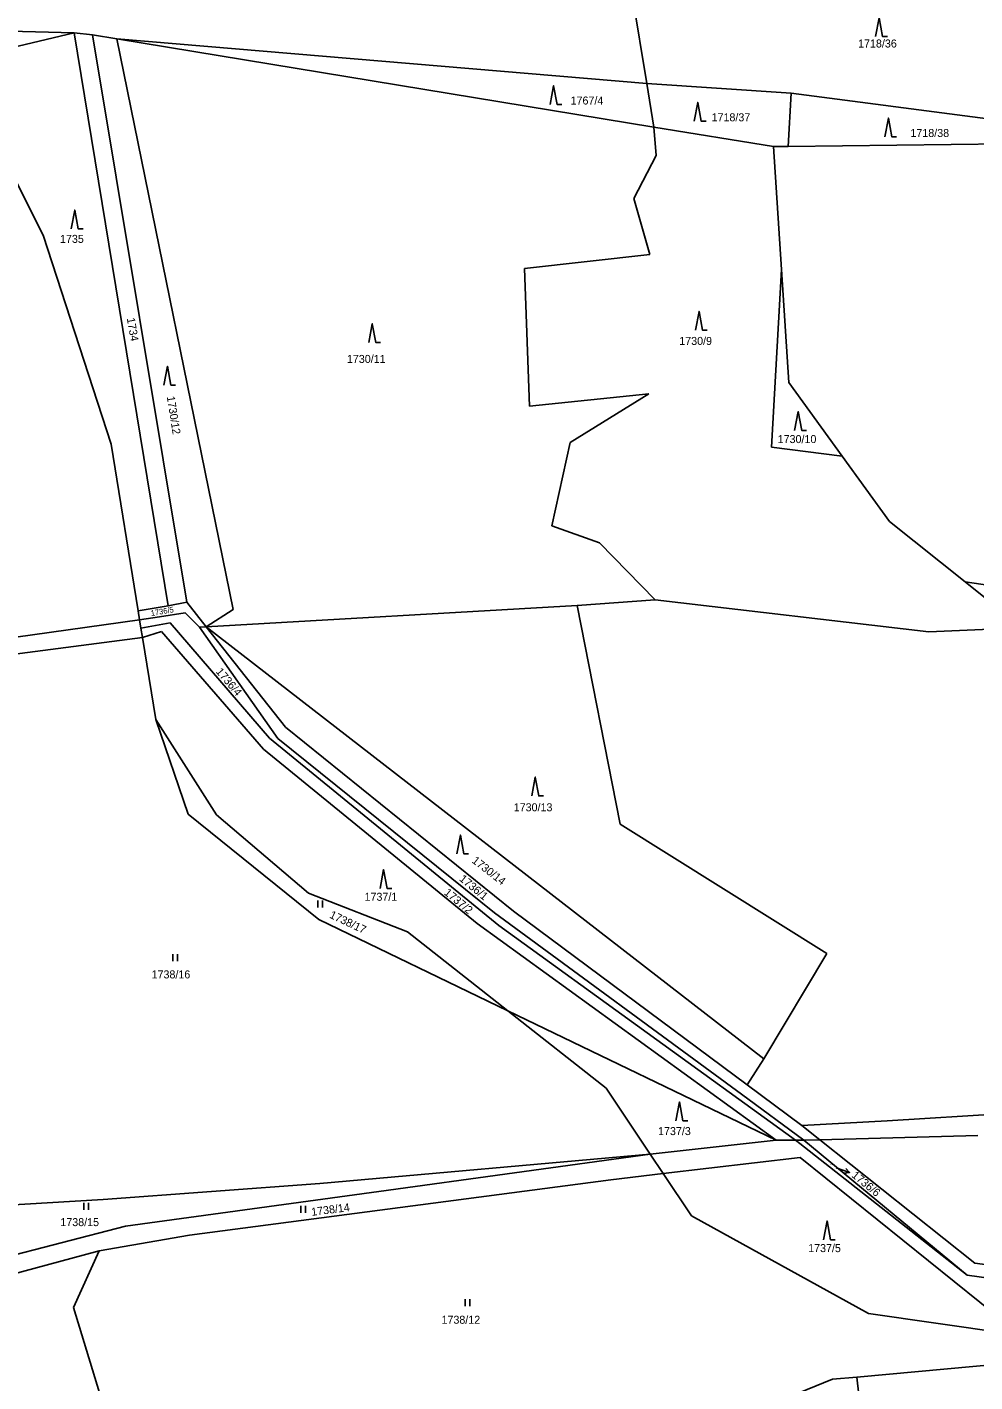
# Model space of a CAD drawing. Extents: x -609861 to -605046, y -1120287 to -1116307.
# Drawn here: x -609113.7 to -608912.5, y -1119290.5 to -1119002.8 of the extents above; entities that cross this region are included whole.
import ezdxf

# ---------------------------------------------------------------- set-up
doc = ezdxf.new("R2010")
doc.units = 0
for name, color, linetype in [('Vrstva 1', 7, 'Continuous'), ('Vrstva 2', 7, 'Continuous'), ('Vrstva 3', 7, 'Continuous'), ('Vrstva 7', 7, 'Continuous')]:
    doc.layers.add(name, color=color, linetype=linetype)

msp = doc.modelspace()

# ---------------------------------------------------------------- linework, layer by layer
at = {"layer": 'Vrstva 1'}
for p, q in [((-608982.13, -1119014.72), (-608989.22, -1118971.97)), ((-609131.7, -1119003.25), (-609103.64, -1119004)), ((-609103.64, -1119004), (-609128.87, -1119009.93)), ((-609099.81, -1119004.44), (-609103.64, -1119004)), ((-609083.72, -1119125.64), (-609103.64, -1119004)), ((-609094.64, -1119005.29), (-609099.81, -1119004.44)), ((-609079.74, -1119124.87), (-609099.81, -1119004.44)), ((-608982.13, -1119014.72), (-609094.64, -1119005.29)), ((-608980.59, -1119023.99), (-609094.64, -1119005.29)), ((-609094.64, -1119005.29), (-609069.91, -1119126.41)), ((-609110.25, -1119046.93), (-609128.87, -1119009.93)), ((-608982.13, -1119014.72), (-608951.45, -1119016.8)), ((-608980.59, -1119023.99), (-608982.13, -1119014.72)), ((-608952.08, -1119028.1), (-608951.45, -1119016.8)), ((-608951.45, -1119016.8), (-608909.69, -1119022.23)), ((-608980.16, -1119030.01), (-608980.59, -1119023.99)), ((-608955.23, -1119028.14), (-608980.59, -1119023.99)), ((-608952.08, -1119028.1), (-608955.23, -1119028.14)), ((-608955.23, -1119028.14), (-608953.52, -1119054.24)), ((-608849.32, -1119026.95), (-608952.08, -1119028.1)), ((-608984.88, -1119039.15), (-608980.16, -1119030.01)), ((-608981.44, -1119051.07), (-608984.88, -1119039.15)), ((-609095.85, -1119091.35), (-609110.25, -1119046.93)), ((-609008.06, -1119054.05), (-608981.44, -1119051.07)), ((-609006.99, -1119083.26), (-609008.06, -1119054.05)), ((-608955.61, -1119091.96), (-608953.52, -1119054.24)), ((-608953.52, -1119054.24), (-608951.95, -1119078.26)), ((-608981.66, -1119080.67), (-609006.99, -1119083.26)), ((-608998.4, -1119091), (-608981.66, -1119080.67)), ((-608951.95, -1119078.26), (-608940.64, -1119093.87)), ((-609090.09, -1119126.71), (-609095.85, -1119091.35)), ((-609002.27, -1119108.69), (-608998.4, -1119091)), ((-608940.64, -1119093.87), (-608955.61, -1119091.96)), ((-608940.64, -1119093.87), (-608930.6, -1119107.73)), ((-608992.18, -1119112.26), (-609002.27, -1119108.69)), ((-608930.6, -1119107.73), (-608914.57, -1119120.58)), ((-608980.37, -1119124.38), (-608992.18, -1119112.26)), ((-608859.5, -1119128.5), (-608914.57, -1119120.58)), ((-608914.57, -1119120.58), (-608902.38, -1119130.35)), ((-609083.72, -1119125.64), (-609090.09, -1119126.71)), ((-609089.78, -1119128.6), (-609090.09, -1119126.71)), ((-609079.74, -1119124.87), (-609083.72, -1119125.64)), ((-609075.62, -1119130.1), (-609079.74, -1119124.87)), ((-609075.62, -1119130.1), (-608996.93, -1119125.62)), ((-609069.91, -1119126.41), (-609075.62, -1119130.1)), ((-608996.93, -1119125.62), (-608980.37, -1119124.38)), ((-608987.74, -1119172.03), (-608996.93, -1119125.62)), ((-608980.37, -1119124.38), (-608922.25, -1119131.21)), ((-609089.78, -1119128.6), (-609167.83, -1119139.65)), ((-609085.55, -1119128), (-609089.78, -1119128.6)), ((-609089.49, -1119130.38), (-609089.78, -1119128.6)), ((-609083.32, -1119129.28), (-609089.49, -1119130.38)), ((-609080.1, -1119127.16), (-609085.55, -1119128)), ((-609062.21, -1119153.74), (-609083.32, -1119129.28)), ((-609077.04, -1119130.18), (-609080.1, -1119127.16)), ((-609089.17, -1119132.38), (-609147.89, -1119140.02)), ((-609089.17, -1119132.38), (-609089.49, -1119130.38)), ((-609089.17, -1119132.38), (-609085.13, -1119131.14)), ((-609086.34, -1119149.77), (-609089.17, -1119132.38)), ((-609085.13, -1119131.14), (-609063.51, -1119156.12)), ((-609075.62, -1119130.1), (-609077.04, -1119130.18)), ((-609060.45, -1119153.85), (-609077.04, -1119130.18)), ((-609058.8, -1119151.45), (-609075.62, -1119130.1)), ((-608957.29, -1119221.83), (-609075.62, -1119130.1)), ((-608922.25, -1119131.21), (-608902.38, -1119130.35)), ((-609079.46, -1119169.88), (-609086.34, -1119149.77)), ((-609073.46, -1119170.01), (-609086.34, -1119149.77)), ((-609010.38, -1119190.48), (-609058.8, -1119151.45)), ((-609013.5, -1119193.51), (-609062.21, -1119153.74)), ((-609014.45, -1119190.88), (-609060.45, -1119153.85)), ((-609063.51, -1119156.12), (-609018.13, -1119193.15)), ((-609051.71, -1119192.3), (-609079.46, -1119169.88)), ((-609053.95, -1119186.7), (-609073.46, -1119170.01)), ((-608943.9, -1119199.48), (-608987.74, -1119172.03)), ((-609032.91, -1119194.86), (-609053.95, -1119186.7)), ((-609011.59, -1119211.65), (-609051.71, -1119192.3)), ((-609018.13, -1119193.15), (-608954.62, -1119239.13)), ((-608962.02, -1119229.34), (-609014.45, -1119190.88)), ((-608960.8, -1119227.4), (-609010.38, -1119190.48)), ((-609011.59, -1119211.65), (-609032.91, -1119194.86)), ((-608950.54, -1119239.14), (-609013.5, -1119193.51)), ((-608957.29, -1119221.83), (-608943.9, -1119199.48)), ((-608954.62, -1119239.13), (-609011.59, -1119211.65)), ((-608990.73, -1119228.08), (-609011.59, -1119211.65)), ((-608960.8, -1119227.4), (-608957.29, -1119221.83)), ((-608949.19, -1119236.04), (-608960.8, -1119227.4)), ((-608981.37, -1119242.11), (-608990.73, -1119228.08)), ((-608948.75, -1119239.14), (-608962.02, -1119229.34)), ((-608931.11, -1119235), (-608864.15, -1119230.95)), ((-608949.19, -1119236.04), (-608931.11, -1119235)), ((-608945.41, -1119239.05), (-608949.19, -1119236.04)), ((-608954.62, -1119239.13), (-608981.37, -1119242.11)), ((-608950.54, -1119239.14), (-608954.62, -1119239.13)), ((-608948.75, -1119239.14), (-608950.54, -1119239.14)), ((-608949.6, -1119239.82), (-608950.54, -1119239.14)), ((-608945.41, -1119239.05), (-608948.75, -1119239.14)), ((-608948.75, -1119239.14), (-608914.13, -1119267.8)), ((-608911.88, -1119238.11), (-608945.41, -1119239.05)), ((-608912.5, -1119265.23), (-608945.41, -1119239.05)), ((-608981.37, -1119242.11), (-609051.54, -1119248.34)), ((-608981.37, -1119242.11), (-609038.99, -1119250.06)), ((-608978.62, -1119246.24), (-608981.37, -1119242.11)), ((-608914.13, -1119267.8), (-608949.6, -1119239.82)), ((-608978.62, -1119246.24), (-608949.58, -1119242.79)), ((-608949.58, -1119242.79), (-608902.64, -1119280.62)), ((-609079.22, -1119259.28), (-608989.72, -1119247.55)), ((-608989.72, -1119247.55), (-608978.62, -1119246.24)), ((-608972.62, -1119255.22), (-608978.62, -1119246.24)), ((-609051.54, -1119248.34), (-609097.54, -1119251.74)), ((-609038.99, -1119250.06), (-609092.75, -1119257.4)), ((-609097.54, -1119251.74), (-609121.14, -1119253.15)), ((-608935.03, -1119275.94), (-608972.62, -1119255.22)), ((-609092.75, -1119257.4), (-609120.66, -1119264.59)), ((-609098.34, -1119262.65), (-609079.22, -1119259.28)), ((-609120.49, -1119268.57), (-609098.34, -1119262.65)), ((-609098.34, -1119262.65), (-609103.8, -1119274.67)), ((-608887.71, -1119271.4), (-608914.13, -1119267.8)), ((-608885.64, -1119268.88), (-608912.5, -1119265.23)), ((-609103.8, -1119274.67), (-609095.64, -1119301.49)), ((-608902.64, -1119280.62), (-608935.03, -1119275.94)), ((-608896.35, -1119285.7), (-608937.56, -1119289.47)), ((-608942.71, -1119289.87), (-608953.44, -1119294.24)), ((-608937.56, -1119289.47), (-608942.71, -1119289.87)), ((-608937.56, -1119289.47), (-608931.03, -1119344.43))]:
    msp.add_line(p, q, dxfattribs=at)
at = {"layer": 'Vrstva 3'}
for p, q in [((-609051.97, -1119188.24), (-609051.97, -1119189.74)), ((-609050.97, -1119189.74), (-609050.97, -1119188.24)), ((-609082.71, -1119199.61), (-609082.71, -1119201.11)), ((-609081.71, -1119201.11), (-609081.71, -1119199.61)), ((-609101.64, -1119252.42), (-609101.64, -1119253.92)), ((-609100.64, -1119253.92), (-609100.64, -1119252.42)), ((-609055.56, -1119253.09), (-609055.56, -1119254.59)), ((-609054.56, -1119254.59), (-609054.56, -1119253.09)), ((-609020.67, -1119272.9), (-609020.67, -1119274.4)), ((-609019.67, -1119274.4), (-609019.67, -1119272.9))]:
    msp.add_line(p, q, dxfattribs=at)
for points in [[(-608933.55, -1119004.77), (-608932.8, -1119000.77), (-608932.05, -1119004.77), (-608931.05, -1119004.77)], [(-609002.64, -1119019.21), (-609001.89, -1119015.21), (-609001.14, -1119019.21), (-609000.14, -1119019.21)], [(-608972.04, -1119022.77), (-608971.29, -1119018.77), (-608970.54, -1119022.77), (-608969.54, -1119022.77)], [(-608931.59, -1119026.1), (-608930.84, -1119022.1), (-608930.09, -1119026.1), (-608929.09, -1119026.1)], [(-609104.29, -1119045.63), (-609103.54, -1119041.63), (-609102.79, -1119045.63), (-609101.79, -1119045.63)], [(-608971.77, -1119067.14), (-608971.02, -1119063.14), (-608970.27, -1119067.14), (-608969.27, -1119067.14)], [(-609041.13, -1119069.77), (-609040.38, -1119065.77), (-609039.63, -1119069.77), (-609038.63, -1119069.77)], [(-609084.64, -1119078.79), (-609083.89, -1119074.79), (-609083.14, -1119078.79), (-609082.14, -1119078.79)], [(-608950.73, -1119088.4), (-608949.98, -1119084.4), (-608949.23, -1119088.4), (-608948.23, -1119088.4)], [(-609006.55, -1119166.02), (-609005.8, -1119162.02), (-609005.05, -1119166.02), (-609004.05, -1119166.02)], [(-609022.44, -1119178.34), (-609021.69, -1119174.34), (-609020.94, -1119178.34), (-609019.94, -1119178.34)], [(-609038.75, -1119185.67), (-609038, -1119181.67), (-609037.25, -1119185.67), (-609036.25, -1119185.67)], [(-608975.94, -1119235), (-608975.19, -1119231), (-608974.44, -1119235), (-608973.44, -1119235)], [(-608944.6, -1119260.29), (-608943.85, -1119256.29), (-608943.1, -1119260.29), (-608942.1, -1119260.29)]]:
    msp.add_lwpolyline(points, dxfattribs=at)
at = {"layer": 'Vrstva 7'}
msp.add_line((-608939.053, -1119245.966), (-608941.89, -1119244.99), dxfattribs=at)
msp.add_lwpolyline([(-608939.836, -1119245.168), (-608939.053, -1119245.966), (-608940.161, -1119246.114)], dxfattribs=at)

# ---------------------------------------------------------------- texts
at = {"layer": 'Vrstva 2'}
for s, height, p in [('1718/36', 1.7, (-608937.267, -1119007.1)), ('1767/4', 1.7, (-608998.297, -1119019.21)), ('1718/37', 1.7, (-608968.367, -1119022.77)), ('1718/38', 1.7, (-608926.157, -1119026.1)), ('1735', 1.7, (-609106.677, -1119048.59)), ('1730/9', 1.7, (-608975.227, -1119070.26)), ('1730/11', 1.7, (-609045.777, -1119074.08)), ('1730/10', 1.7, (-608954.337, -1119091.1)), ('1730/13', 1.7, (-609010.367, -1119169.29)), ('1737/1', 1.7, (-609042.037, -1119188.29)), ('1738/16', 1.7, (-609087.237, -1119204.78)), ('1737/3', 1.7, (-608979.727, -1119238.05)), ('1736/6', 0.2, (-608943.364, -1119244.42)), ('1738/15', 1.7, (-609106.607, -1119257.38)), ('1737/5', 1.7, (-608947.867, -1119262.9)), ('1738/12', 1.7, (-609025.697, -1119278.11))]:
    msp.add_text(s, height=height, dxfattribs=at).set_placement(p)
for s, height, rotation, p in [('1734', 1.7, 279.88988, (-609092.503, -1119064.617)), ('1730/12', 1.7, 278.97315, (-609084.019, -1119081.248)), ('1736/5', 1.2, 9.91217, (-609087.297, -1119127.852)), ('1736/4', 1.7, 310.48583, (-609073.705, -1119139.699)), ('1730/14', 1.7, 322.17417, (-609019.39, -1119180.051)), ('1736/1', 1.7, 320.398, (-609022.057, -1119183.87)), ('1737/2', 1.7, 320.398, (-609025.297, -1119186.81)), ('1738/17', 1.7, 334.77924, (-609049.615, -1119191.837)), ('1738/14', 1.7, 7.21927, (-609053.24, -1119255.211))]:
    msp.add_text(s, height=height, rotation=rotation, dxfattribs=at).set_placement(p)
at = {"layer": 'Vrstva 7'}
msp.add_text('1736/6', height=1.7, rotation=320.398, dxfattribs=at).set_placement((-608938.769, -1119246.815))

doc.saveas('drawing.dxf')
